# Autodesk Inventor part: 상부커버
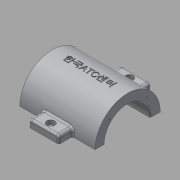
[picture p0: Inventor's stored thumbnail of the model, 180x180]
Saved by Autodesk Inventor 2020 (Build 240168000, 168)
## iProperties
Created: 2015-12
Part Number: 상부커버
Material: 알루미늄 6061
Document SubType Name: Modeling
Designer: mduedu
Density: 2.71 g/cm^3
Mass: 189.929 g
Surface Area: 186.965 cm^2
Volume: 70.0843 cm^3
Appearance: 알루미늄 - 평지
Author: mduedu
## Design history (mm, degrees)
sketch "스케치1"
  geometry: L1 (45, 40)-(-45, 40); L2 (-45, 40)-(-45, -40); L3 (-45, -40)-(45, -40); L4 (45, -40)-(45, 40); L5 (45, 40)-(-45, -40); L6 (-45, 40)-(45, -40); 2 further points
  constraints: 12 end point, 2 midpoint, 2 parallel, 1 coincident, 1 horizontal, 1 perpendicular, 3 other
  dimensions: "d0" = 90 distance of L2.end L3.end; "d2" = 80 distance of L1.end L2.end
extrude "돌출1" new body sketch "스케치1" distance "d3" = 10; taper "d4" = 0 deg
sketch "스케치2"
  geometry: C1 r 32.5 at (80, 0); 1 further point
  constraints: 1 centre point
  dimensions: "d5" = 65 diameter of C1; "d116" = 80 distance of point (0, 0) C1.centre
extrude "돌출2" join sketch "스케치2" stored distance "d7" = 75; taper "d8" = 0 deg
sketch "스케치3"
  geometry: L1 (-27.5, -20)-(27.5, -20); L2 (27.5, -20)-(27.5, 20); L3 (27.5, 20)-(-27.5, 20); L4 (-27.5, 20)-(-27.5, -20); L5 (-27.5, -20)-(27.5, 20); L6 (27.5, -20)-(-27.5, 20); 1 further point
  constraints: 12 end point, 2 midpoint, 2 parallel, 1 horizontal, 1 perpendicular
  dimensions: "d9" = 55 distance of L2.end L3.end; "d11" = 40 distance of L1.end L2.end
extrude "돌출3" new body sketch "스케치3" stored distance "d12" = 75; taper "d13" = 0 deg
fillet "모깎기1"
fillet "모깎기2"
feature "결합1"
  node "솔리드2"
sketch "스케치4"
  geometry: L1 (-37.5, 47.5)-(37.5, 47.5) reference; L2 (32.5, 47.5)-(40.208, 10); L3 (37.5, 47.5)-(37.5, 112.5) reference; L4 (60.208, 0)-(60.208, 10) reference; L5 (60.208, 10)-(-60.208, 10) reference; 1 further point
  constraints: 2 end point, 2 point on line
  dimensions: "d15" = 5 distance from line of L2.start L3; "d117" = 20 distance from line of L2.end L4
sketch "스케치5"
  geometry: L1 (10, 35.208)-(56.729, 22.687); L2 (0, 60.208)-(10, 60.208) reference; L3 (10, -60.208)-(10, 60.208) reference; 2 further points
  constraints: 2 end point, 1 point on line, 2 other
  dimensions: "d118" = 25 distance from line of L1.start L2; "d119" = 75 deg angle of L1 L3
feature "리브1" dims "d19" = 1, "d20" = 6, "d21" = 0, "d22" = 0, "d23" = 1, "d24" = 1
feature "리브2" dims "d25" = 1, "d26" = 6, "d27" = 0, "d28" = 0, "d29" = 1, "d30" = 1
fillet "모깎기4" dims "d31" = 2
fillet "모깎기5" dims "d32" = 2
fillet "모깎기6" dims "d33" = 2
sketch "스케치6"
  geometry: L1 (0, 0)-(-32.88, 32.88); L2 (0, 0)-(-46.5, 0); A1 r 46.5 centre (0, 0) between (-32.88, 32.88) and (-46.5, 0); 5 further points
  constraints: 4 end point, 2 coincident, 2 point on circle, 1 centre point, 1 horizontal, 5 other
  dimensions: "d120" = 93 diameter of A1; "d122" = 45 deg angle of L1 L2; "d126" = 360 deg dimension on point (0, 0) point (-32.88, 32.88) (derived)
hole "구멍1" sketch "스케치6" at (-32.88, 32.88), (-32.88, -32.88), (32.88, -32.88), (32.88, 32.88) diameter "d34" = 7; stored, may be unused: countersink angle "d38" = 90 deg, drill point angle "d40" = 118 deg; dims "d35" = 6, "d36" = 12, "d37" = 3, "d39" = 8
fillet "모깎기13" dims "d131" = 3
hole "구멍2" diameter "d44" = 45; stored, may be unused: countersink angle "d48" = 90 deg, drill point angle "d50" = 118 deg; dims "d42" = 10, "d43" = 10, "d45" = 6, "d46" = 4, "d47" = 2, "d49" = 8
sketch "스케치7" dims "d52" = 26.5
  geometry: L1 (0, 0)-(32.5, 0); L2 (0, 0)-(22.981, 22.981); A1 r 32.5 centre (0, 0) between (32.5, 0) and (22.981, 22.981) reference; 3 further points
  constraints: 4 end point, 2 point on circle, 1 coincident, 1 horizontal, 1 point on line, 3 other
  dimensions: "d51" = 45 deg angle of L2 L1
hole "구멍3" sketch "스케치7" at (18.738, 18.738) diameter "d54" = 2.459; stored, may be unused: countersink angle "d58" = 90 deg, drill point angle "d60" = 118 deg; dims "d55" = 8, "d56" = 4, "d57" = 2, "d59" = 10
sketch "스케치8"
  geometry: L1 (72.5, 31.623)-(72.5, 46); L2 (72.5, 46)-(87.5, 46); L3 (87.5, 46)-(87.5, 31.623); A1 r 32.5 centre (80, 0) between (87.5, 31.623) and (72.5, 31.623) reference; 2 further points
  constraints: 6 end point, 2 point on circle, 1 horizontal, 1 midpoint, 1 parallel, 1 vertical, 1 vertical alignment
  dimensions: "d64" = 15 distance of L1.end L2.end; "d66" = 46 distance from line of L2 A1.centre
extrude "돌출4" join sketch "스케치8" stored distance "d67" = 30; taper "d68" = 0 deg
fillet "모깎기8" dims "d69" = 3
fillet "모깎기9" dims "d70" = 2
node "작업 평면2"
sketch "스케치16"
  geometry: L1 (33.166, 72.5)-(44, 72.5) reference; L2 (42.5, 72.5)-(28.53, 64.434); L3 (46, 75.5)-(46, 84.5) reference; 2 further points
  constraints: 2 end point, 1 point on line, 2 other
  dimensions: "d138" = 30 deg angle of L2 L1; "d139" = 3.5 distance from line of L2.start L3
feature "리브3" sketch "스케치16" dims "d140" = 1, "d141" = 3, "d142" = 0, "d143" = 0, "d144" = 1, "d145" = 1
fillet "모깎기14" dims "d146" = 1
fillet "모깎기15" dims "d147" = 1
sketch "스케치9"
  geometry: L1 (-76, -110)-(76, -110); L2 (76, -110)-(76, 0); L3 (76, 0)-(-76, 0); L4 (-76, 0)-(-76, -110); L5 (-46, 4.5)-(-46, -4.5) reference; L6 (-60.208, -80)-(60.208, -80) reference; C1 r 32.5 at (0, 0) reference; 2 further points
  constraints: 8 end point, 2 parallel, 1 coincident, 1 horizontal, 1 midpoint, 1 perpendicular
  dimensions: "d72" = 30 distance between parallel lines of L4 L5; "d148" = 30 distance between parallel lines of L6 L1
extrude "돌출5" cut sketch "스케치9" extent not by distance; stored distance "d73" = 0; taper "d74" = 0 deg
node "작업 평면3"
sketch "스케치17"
  geometry: 2 further points
  constraints: 1 coincident, 1 other
feature "엠보싱1" sketch "스케치17" dims "d12" = 75, "d13" = 0, "d150" = 0.5, "d151" = 0
sketch "스케치18"
  geometry: L1 (-3, -1.039)-(-3, -10.834) reference; L2 (27, -10.834)-(27, -1.039) reference; L3 (0, -12.834)-(24, -12.834) reference; L4 (-3, -5.936)-(27, -5.936); L5 (12, -12.834)-(12, 33.166); 1 further point
  constraints: 4 end point, 4 midpoint, 1 perpendicular, 1 point on line
hole "구멍8" sketch "스케치18" at (12, -5.936) diameter "d152" = 4.5; stored, may be unused: countersink angle "d156" = 90 deg, drill point angle "d158" = 118 deg; dims "d153" = 6, "d154" = 8, "d155" = 4.6, "d157" = 8
chamfer "모따기2" distance "d159" = 1; stored, may be unused: second distance "d160" = 2, angle "d161" = 45 deg
node "솔리드1"
mirror "대칭1"
mirror "대칭2"
pattern_circular "원형 패턴1" dims angle "d62" = 360 deg
mirror "대칭3"
mirror "대칭7"
mirror "대칭4"
mirror "대칭8"
other parameters: "d137" = -5
